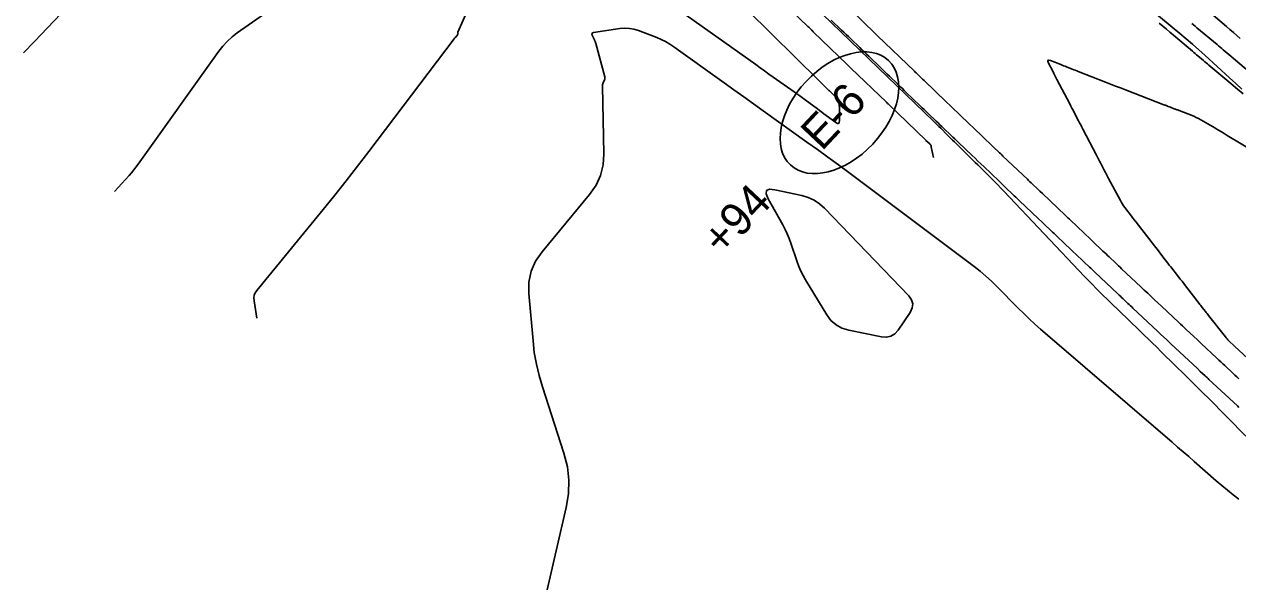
# Model space of a CAD drawing. Extents: x 1005228 to 1008882, y 1883389 to 1885754.
# Drawn here: x 1007015.2 to 1007247.3, y 1885165.6 to 1885273.6 of the extents above; entities that cross this region are included whole.
import ezdxf

# ---------------------------------------------------------------- set-up
doc = ezdxf.new("R2010")
doc.units = 0
for name, color, linetype in [('ATDIMS', 7, 'Continuous'), ('C-ANNO-NOTE', 7, 'Continuous'), ('R_Erosion', 7, 'Continuous'), ('S_BASELINE', 7, 'Continuous'), ('S_BRIDGE', 7, 'Continuous'), ('TSOBSTACLE', 7, 'Continuous')]:
    doc.layers.add(name, color=color, linetype=linetype)

msp = doc.modelspace()

# ---------------------------------------------------------------- linework, layer by layer
at = {"layer": 'ATDIMS'}
msp.add_lwpolyline([(1007253.99, 1885205.32), (1007246.77, 1885212.05), (1007246.71, 1885212.11), (1007245.62, 1885213.13), (1007245.44, 1885213.3), (1007245.27, 1885213.48), (1007245.1, 1885213.67), (1007244.95, 1885213.86), (1007241.72, 1885217.99), (1007241.57, 1885218.18), (1007241.43, 1885218.37), (1007241.28, 1885218.56), (1007241.13, 1885218.75), (1007240.53, 1885219.52), (1007240.38, 1885219.71), (1007240.23, 1885219.9), (1007240.08, 1885220.09), (1007239.93, 1885220.28), (1007237.32, 1885223.64), (1007236.98, 1885224.07), (1007236.65, 1885224.5), (1007236.31, 1885224.93), (1007235.98, 1885225.36), (1007234.49, 1885227.28), (1007234.22, 1885227.61), (1007233.96, 1885227.95), (1007233.7, 1885228.28), (1007233.44, 1885228.62), (1007232.4, 1885229.96), (1007232.14, 1885230.3), (1007231.88, 1885230.63), (1007231.62, 1885230.97), (1007231.36, 1885231.31), (1007227.86, 1885235.81), (1007227.79, 1885235.91), (1007227.71, 1885236), (1007227.64, 1885236.1), (1007227.56, 1885236.2), (1007227.27, 1885236.58), (1007227.12, 1885236.77), (1007226.97, 1885236.96), (1007225.69, 1885238.62), (1007225.46, 1885238.93), (1007225.25, 1885239.25), (1007225.05, 1885239.58), (1007224.86, 1885239.92), (1007222.62, 1885244.17), (1007222.42, 1885244.54), (1007222.23, 1885244.91), (1007222.04, 1885245.27), (1007221.84, 1885245.64), (1007221.08, 1885247.11), (1007220.88, 1885247.48), (1007220.69, 1885247.84), (1007220.5, 1885248.21), (1007220.31, 1885248.58), (1007217.69, 1885253.57), (1007217.48, 1885253.97), (1007217.27, 1885254.38), (1007217.06, 1885254.78), (1007216.85, 1885255.18), (1007216.01, 1885256.79), (1007215.8, 1885257.19), (1007215.59, 1885257.59), (1007215.38, 1885257.99), (1007215.17, 1885258.4), (1007212.73, 1885263.06), (1007212.53, 1885263.45), (1007212.32, 1885263.85), (1007212.12, 1885264.24), (1007211.91, 1885264.64), (1007211.09, 1885266.22), (1007210.96, 1885266.54), (1007210.99, 1885266.73), (1007211.17, 1885266.78), (1007211.51, 1885266.68), (1007213.44, 1885265.93), (1007213.72, 1885265.82), (1007213.99, 1885265.71), (1007214.27, 1885265.6), (1007214.55, 1885265.49), (1007215.67, 1885265.05), (1007215.95, 1885264.94), (1007216.23, 1885264.83), (1007216.51, 1885264.72), (1007216.79, 1885264.62), (1007222.01, 1885262.57), (1007222.97, 1885262.2), (1007223.94, 1885261.82), (1007224.9, 1885261.45), (1007225.86, 1885261.08), (1007233.19, 1885258.25), (1007233.26, 1885258.22), (1007233.33, 1885258.19), (1007233.4, 1885258.17), (1007233.47, 1885258.14), (1007233.75, 1885258.03), (1007233.82, 1885258), (1007233.89, 1885257.97), (1007233.96, 1885257.95), (1007234.03, 1885257.92), (1007234.45, 1885257.76), (1007234.55, 1885257.72), (1007234.64, 1885257.69), (1007234.73, 1885257.65), (1007234.83, 1885257.61), (1007235.32, 1885257.42), (1007235.44, 1885257.38), (1007235.55, 1885257.33), (1007235.66, 1885257.29), (1007235.78, 1885257.24), (1007238.91, 1885256.03), (1007239.37, 1885255.83), (1007239.83, 1885255.62), (1007240.28, 1885255.39), (1007240.72, 1885255.13), (1007242.94, 1885253.8), (1007243.13, 1885253.68), (1007243.33, 1885253.56), (1007243.53, 1885253.44), (1007243.73, 1885253.33), (1007244.52, 1885252.85), (1007244.72, 1885252.73), (1007244.91, 1885252.61), (1007245.11, 1885252.5), (1007245.31, 1885252.38), (1007250.65, 1885249.17)], dxfattribs=at)
at = {"layer": 'C-ANNO-NOTE'}
for points in [[(1007059.68, 1885217.46), (1007059.16, 1885220.79), (1007059.12, 1885221.33), (1007059.2, 1885221.84), (1007059.39, 1885222.32), (1007059.69, 1885222.77), (1007072.38, 1885238.23), (1007074.6, 1885240.97), (1007076.8, 1885243.72), (1007078.97, 1885246.49), (1007081.11, 1885249.29), (1007097.47, 1885270.86), (1007097.53, 1885270.94), (1007097.59, 1885271.02), (1007097.66, 1885271.1), (1007097.73, 1885271.18), (1007098.06, 1885271.59), (1007098.09, 1885271.63), (1007098.11, 1885271.67), (1007098.12, 1885271.71), (1007098.12, 1885271.75), (1007098.12, 1885271.93), (1007098.12, 1885271.98), (1007098.13, 1885272.02), (1007098.14, 1885272.07), (1007098.15, 1885272.11), (1007103.57, 1885284.34)], [(1007248.11, 1885261.21), (1007246.93, 1885262.29), (1007245.76, 1885263.37), (1007241.04, 1885267.69), (1007239.86, 1885268.76), (1007238.66, 1885269.82), (1007237.45, 1885270.86), (1007236.23, 1885271.89), (1007222.57, 1885283.19)], [(1007015.08, 1885268.17), (1007015.76, 1885268.89), (1007016.45, 1885269.62), (1007017.14, 1885270.34), (1007027.17, 1885280.9)], [(1007140.29, 1885276.46), (1007155.11, 1885265.91), (1007155.95, 1885265.31), (1007156.79, 1885264.71), (1007157.63, 1885264.11), (1007158.47, 1885263.51), (1007162.45, 1885260.69), (1007162.99, 1885260.31), (1007163.52, 1885259.93), (1007164.05, 1885259.54), (1007164.58, 1885259.16), (1007166.9, 1885257.45), (1007167.32, 1885257.14), (1007167.75, 1885256.83), (1007168.17, 1885256.51), (1007168.6, 1885256.2), (1007170.42, 1885254.86), (1007170.74, 1885254.68), (1007170.96, 1885254.68), (1007171.1, 1885254.86), (1007171.14, 1885255.22), (1007171.12, 1885257.61), (1007171.12, 1885257.77), (1007171.11, 1885257.92), (1007171.1, 1885258.07), (1007171.09, 1885258.22), (1007171.02, 1885258.83), (1007171, 1885258.98), (1007170.95, 1885259.11), (1007170.87, 1885259.23), (1007170.78, 1885259.35), (1007169.9, 1885260.22), (1007169.82, 1885260.3), (1007169.74, 1885260.37), (1007169.67, 1885260.45), (1007169.59, 1885260.52), (1007169.29, 1885260.82), (1007169.21, 1885260.89), (1007169.13, 1885260.96), (1007169.06, 1885261.04), (1007168.98, 1885261.11), (1007160.93, 1885269.04), (1007159.87, 1885270.07), (1007158.82, 1885271.11), (1007157.77, 1885272.15), (1007156.71, 1885273.18), (1007151.27, 1885278.54)], [(1007248.87, 1885194.9), (1007241.62, 1885202.2), (1007240.73, 1885203.09), (1007239.84, 1885203.97), (1007238.95, 1885204.86), (1007238.06, 1885205.74), (1007234.46, 1885209.29), (1007233.58, 1885210.16), (1007232.69, 1885211.02), (1007231.81, 1885211.89), (1007230.92, 1885212.75), (1007226.36, 1885217.18), (1007224.83, 1885218.66), (1007221.01, 1885222.37), (1007220.25, 1885223.11), (1007219.5, 1885223.86), (1007218.76, 1885224.63), (1007218.02, 1885225.39), (1007202.6, 1885241.7), (1007202.01, 1885242.32), (1007201.42, 1885242.93), (1007200.82, 1885243.54), (1007200.21, 1885244.14), (1007197.6, 1885246.73), (1007197.08, 1885247.23), (1007196.57, 1885247.74), (1007196.06, 1885248.25), (1007195.54, 1885248.76), (1007193.11, 1885251.16), (1007192.78, 1885251.48), (1007192.46, 1885251.81), (1007192.13, 1885252.13), (1007191.8, 1885252.46), (1007190.49, 1885253.76), (1007190.16, 1885254.08), (1007189.83, 1885254.41), (1007189.5, 1885254.73), (1007189.17, 1885255.05), (1007164.33, 1885279.04)], [(1007032.48, 1885241.69), (1007035.25, 1885244.74), (1007035.7, 1885245.25), (1007036.14, 1885245.78), (1007036.56, 1885246.32), (1007036.97, 1885246.87), (1007052.42, 1885268.46), (1007053.19, 1885269.45), (1007054.03, 1885270.36), (1007054.95, 1885271.2), (1007055.95, 1885271.96), (1007060.96, 1885275.48)], [(1007115.21, 1885165.56), (1007118.88, 1885181.28), (1007119.31, 1885183.89), (1007119.38, 1885186.49), (1007119.09, 1885189.07), (1007118.43, 1885191.63), (1007114.31, 1885204.34), (1007113.67, 1885206.5), (1007113.16, 1885208.69), (1007112.77, 1885210.91), (1007112.52, 1885213.15), (1007111.74, 1885222.17), (1007111.75, 1885224.36), (1007112.17, 1885226.42), (1007113, 1885228.35), (1007114.24, 1885230.16), (1007123.34, 1885241.09), (1007124.57, 1885242.85), (1007125.44, 1885244.74), (1007125.94, 1885246.75), (1007126.08, 1885248.89), (1007125.81, 1885261.81), (1007125.81, 1885261.96), (1007125.84, 1885262.12), (1007125.87, 1885262.26), (1007125.93, 1885262.41), (1007126.18, 1885262.98), (1007126.23, 1885263.12), (1007126.26, 1885263.27), (1007126.25, 1885263.41), (1007126.23, 1885263.56), (1007124.51, 1885269.93), (1007124.45, 1885270.14), (1007124.38, 1885270.35), (1007124.3, 1885270.56), (1007124.21, 1885270.76), (1007123.84, 1885271.57), (1007123.78, 1885271.75), (1007123.81, 1885271.89), (1007123.91, 1885271.99), (1007124.09, 1885272.04), (1007129.14, 1885272.79), (1007130.05, 1885272.87), (1007130.95, 1885272.83), (1007131.83, 1885272.68), (1007132.7, 1885272.41), (1007136.21, 1885271.08), (1007137.06, 1885270.72), (1007137.89, 1885270.31), (1007138.69, 1885269.84), (1007139.47, 1885269.33), (1007149.1, 1885262.4), (1007150.96, 1885261.07), (1007152.82, 1885259.73), (1007154.68, 1885258.4), (1007156.54, 1885257.07), (1007164.92, 1885251.11), (1007166.93, 1885249.67), (1007168.93, 1885248.21), (1007170.93, 1885246.75), (1007172.91, 1885245.27), (1007196.89, 1885227.33), (1007198.04, 1885226.43), (1007199.15, 1885225.5), (1007200.22, 1885224.52), (1007201.26, 1885223.5), (1007205.34, 1885219.35), (1007206.37, 1885218.32), (1007207.42, 1885217.31), (1007208.5, 1885216.33), (1007209.59, 1885215.37), (1007234.75, 1885193.74), (1007235.81, 1885192.83), (1007236.87, 1885191.91), (1007237.93, 1885190.99), (1007238.98, 1885190.06), (1007243.19, 1885186.37), (1007244.25, 1885185.45), (1007245.33, 1885184.56), (1007246.43, 1885183.69), (1007247.54, 1885182.85)]]:
    msp.add_lwpolyline(points, dxfattribs=at)
at = {"layer": 'R_Erosion'}
msp.add_ellipse((1007171.13, 1885256.71), major_axis=(9.39, 9.97), ratio=0.638788, dxfattribs=at)
at = {"layer": 'S_BRIDGE'}
msp.add_lwpolyline([(1007184.92, 1885220.99), (1007185.14, 1885220.21), (1007185.05, 1885219.4), (1007184.64, 1885218.57), (1007182.34, 1885215.18), (1007181.71, 1885214.47), (1007180.97, 1885214.01), (1007180.13, 1885213.82), (1007179.18, 1885213.89), (1007172.91, 1885215.16), (1007171.61, 1885215.55), (1007170.47, 1885216.18), (1007169.5, 1885217.03), (1007168.69, 1885218.12), (1007164.66, 1885224.75), (1007164.19, 1885225.58), (1007163.77, 1885226.43), (1007163.39, 1885227.3), (1007163.06, 1885228.19), (1007161.83, 1885231.8), (1007161.5, 1885232.69), (1007161.13, 1885233.57), (1007160.73, 1885234.42), (1007160.28, 1885235.27), (1007157.5, 1885240.29), (1007157.11, 1885241.23), (1007157.2, 1885241.83), (1007157.74, 1885242.08), (1007158.76, 1885241.99), (1007163.92, 1885240.88), (1007165.15, 1885240.52), (1007166.28, 1885240), (1007167.33, 1885239.31), (1007168.28, 1885238.45), (1007184.37, 1885221.74)], close=True, dxfattribs=at)
at = {"layer": 'TSOBSTACLE'}
for points in [[(1007189.1, 1885248.17), (1007189, 1885248.67), (1007188.98, 1885248.76), (1007188.97, 1885248.84), (1007188.95, 1885248.93), (1007188.93, 1885249.01), (1007188.7, 1885250.21), (1007188.66, 1885250.36), (1007188.6, 1885250.5), (1007188.51, 1885250.63), (1007188.4, 1885250.75), (1007187.68, 1885251.44), (1007187.63, 1885251.49), (1007180.48, 1885258.35), (1007180.42, 1885258.41), (1007180.35, 1885258.47), (1007180.1, 1885258.71), (1007173.29, 1885265.26), (1007173.23, 1885265.32), (1007173.18, 1885265.38), (1007173.12, 1885265.44), (1007173.06, 1885265.49), (1007172.64, 1885265.9), (1007172.58, 1885265.95), (1007166.12, 1885272.19), (1007166.03, 1885272.28), (1007165.95, 1885272.36), (1007165.86, 1885272.45), (1007165.77, 1885272.53), (1007165.25, 1885273.04), (1007165.07, 1885273.21), (1007158.96, 1885279.13)], [(1007247.54, 1885205.87), (1007247.15, 1885206.23), (1007246.77, 1885206.58), (1007246.38, 1885206.94), (1007244.85, 1885208.38), (1007244.46, 1885208.74), (1007244.08, 1885209.1), (1007243.69, 1885209.45), (1007243.31, 1885209.81), (1007240.3, 1885212.63), (1007239.59, 1885213.29), (1007238.88, 1885213.96), (1007237.46, 1885215.29), (1007237.1, 1885215.62), (1007236.75, 1885215.96), (1007236.39, 1885216.29), (1007236.04, 1885216.62), (1007232.7, 1885219.76), (1007232.04, 1885220.38), (1007231.39, 1885220.99), (1007230.08, 1885222.22), (1007229.76, 1885222.53), (1007229.43, 1885222.83), (1007229.1, 1885223.14), (1007228.78, 1885223.45), (1007225.1, 1885226.91), (1007224.81, 1885227.19), (1007224.51, 1885227.47), (1007224.21, 1885227.75), (1007223.91, 1885228.03), (1007222.72, 1885229.16), (1007222.42, 1885229.44), (1007222.13, 1885229.72), (1007221.83, 1885230), (1007221.53, 1885230.28), (1007217.52, 1885234.07), (1007216.98, 1885234.58), (1007216.45, 1885235.09), (1007215.37, 1885236.11), (1007215.1, 1885236.36), (1007214.83, 1885236.62), (1007214.56, 1885236.87), (1007214.29, 1885237.13), (1007209.96, 1885241.25), (1007209.47, 1885241.7), (1007208.99, 1885242.16), (1007208.03, 1885243.07), (1007207.79, 1885243.3), (1007207.55, 1885243.53), (1007207.31, 1885243.76), (1007207.07, 1885243.99), (1007202.4, 1885248.44), (1007202.19, 1885248.64), (1007201.98, 1885248.84), (1007201.77, 1885249.04), (1007201.55, 1885249.24), (1007200.68, 1885250.07), (1007200.48, 1885250.26), (1007200.28, 1885250.46), (1007200.08, 1885250.65), (1007199.88, 1885250.84), (1007199.09, 1885251.6), (1007198.69, 1885251.98), (1007198.29, 1885252.36), (1007194.44, 1885256.04), (1007193.74, 1885256.72), (1007193.03, 1885257.39), (1007192.32, 1885258.07), (1007191.62, 1885258.75), (1007187.34, 1885262.85), (1007187.03, 1885263.15), (1007186.72, 1885263.45), (1007186.1, 1885264.04), (1007185.94, 1885264.19), (1007185.79, 1885264.34), (1007185.63, 1885264.49), (1007185.48, 1885264.64), (1007179.82, 1885270.08), (1007179.44, 1885270.45), (1007178.81, 1885271.06), (1007178.68, 1885271.18), (1007178.55, 1885271.3), (1007178.43, 1885271.42), (1007178.3, 1885271.55), (1007172.32, 1885277.32)], [(1007247.8, 1885270.92), (1007247.13, 1885271.49), (1007246.47, 1885272.06), (1007245.8, 1885272.63), (1007245.13, 1885273.2), (1007240.49, 1885277.16)], [(1007169.56, 1885274.43), (1007171.55, 1885272.51), (1007171.98, 1885272.09), (1007172.41, 1885271.68), (1007172.84, 1885271.26), (1007173.28, 1885270.84), (1007175, 1885269.17), (1007175.43, 1885268.76), (1007175.87, 1885268.34), (1007176.3, 1885267.92), (1007176.73, 1885267.51), (1007179.06, 1885265.27), (1007179.46, 1885264.88), (1007179.87, 1885264.49), (1007180.27, 1885264.1), (1007180.67, 1885263.71), (1007182.29, 1885262.15), (1007182.7, 1885261.76), (1007183.1, 1885261.38), (1007183.51, 1885260.99), (1007183.91, 1885260.6), (1007186.58, 1885258.04), (1007186.96, 1885257.68), (1007187.33, 1885257.31), (1007187.71, 1885256.95), (1007188.09, 1885256.59), (1007189.64, 1885255.1), (1007189.99, 1885254.76), (1007190.35, 1885254.42), (1007190.7, 1885254.08), (1007191.06, 1885253.74), (1007192.48, 1885252.38), (1007192.84, 1885252.04), (1007193.19, 1885251.7), (1007193.55, 1885251.36), (1007193.9, 1885251.02), (1007196.51, 1885248.54), (1007197.06, 1885248.01), (1007197.61, 1885247.48), (1007198.16, 1885246.95), (1007198.72, 1885246.43), (1007201.66, 1885243.62), (1007201.98, 1885243.31), (1007202.31, 1885243.01), (1007202.63, 1885242.7), (1007202.95, 1885242.39), (1007204.24, 1885241.16), (1007204.56, 1885240.86), (1007204.88, 1885240.55), (1007205.2, 1885240.24), (1007205.53, 1885239.94), (1007209.22, 1885236.43), (1007209.81, 1885235.87), (1007210.4, 1885235.31), (1007211.58, 1885234.19), (1007211.87, 1885233.91), (1007212.17, 1885233.63), (1007212.46, 1885233.36), (1007212.76, 1885233.08), (1007216.8, 1885229.25), (1007217.33, 1885228.75), (1007217.87, 1885228.24), (1007218.93, 1885227.23), (1007219.2, 1885226.98), (1007219.47, 1885226.73), (1007219.73, 1885226.48), (1007220, 1885226.23), (1007224.39, 1885222.09), (1007224.63, 1885221.87), (1007224.86, 1885221.64), (1007225.1, 1885221.42), (1007225.34, 1885221.19), (1007226.3, 1885220.29), (1007226.54, 1885220.06), (1007226.78, 1885219.84), (1007227.02, 1885219.61), (1007227.26, 1885219.39), (1007231.99, 1885214.94), (1007232.62, 1885214.35), (1007233.68, 1885213.36), (1007233.89, 1885213.16), (1007234.1, 1885212.96), (1007234.31, 1885212.76), (1007234.52, 1885212.56), (1007239.6, 1885207.81), (1007240.15, 1885207.29), (1007241.07, 1885206.44), (1007241.25, 1885206.26), (1007241.43, 1885206.09), (1007241.62, 1885205.92), (1007241.8, 1885205.75), (1007247.23, 1885200.68), (1007247.54, 1885200.4)], [(1007232.27, 1885273.83), (1007232.96, 1885273.25), (1007233.65, 1885272.67), (1007234.34, 1885272.09), (1007235.03, 1885271.51), (1007238.64, 1885268.48), (1007238.9, 1885268.25), (1007239.16, 1885268.03), (1007239.43, 1885267.81), (1007239.69, 1885267.59), (1007240.75, 1885266.7), (1007241.02, 1885266.47), (1007241.28, 1885266.25), (1007241.55, 1885266.03), (1007241.81, 1885265.81), (1007245.99, 1885262.3), (1007246.87, 1885261.56), (1007248.33, 1885260.34)], [(1007238.55, 1885273.77), (1007238.87, 1885273.51), (1007239.19, 1885273.24), (1007239.51, 1885272.97), (1007243.36, 1885269.73), (1007243.65, 1885269.48), (1007243.94, 1885269.24), (1007244.24, 1885268.99), (1007244.53, 1885268.75), (1007245.98, 1885267.53), (1007246.86, 1885266.79), (1007251.05, 1885263.28)]]:
    msp.add_lwpolyline(points, dxfattribs=at)

# ---------------------------------------------------------------- texts
at = {"layer": 'R_Erosion'}
msp.add_text('E-6', height=6.25, rotation=46.7161, dxfattribs=at).set_placement((1007167.75, 1885249.24))
at = {"layer": 'S_BASELINE'}
msp.add_text('+94', height=6.25, rotation=46.7161, dxfattribs=at).set_placement((1007148.75, 1885229.06))

doc.saveas('drawing.dxf')
